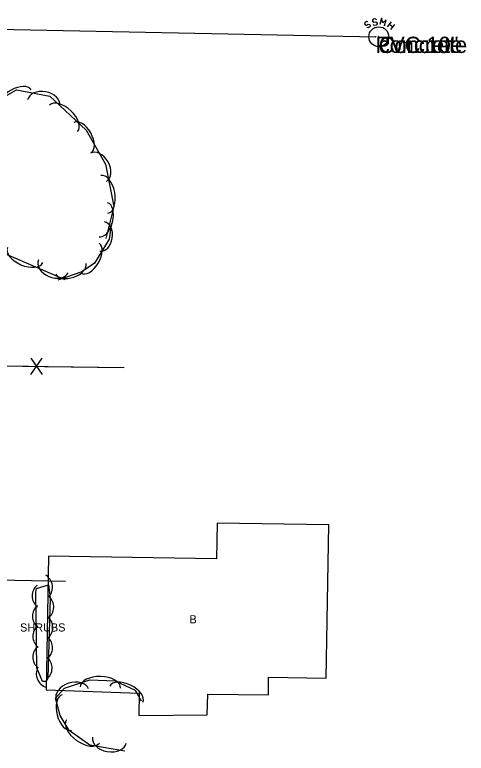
# Model space of a CAD drawing. Extents: x 1802180 to 1804859, y 572524 to 575172.
# Drawn here: x 1803803.6 to 1803942.1, y 574509.5 to 574736.5 of the extents above; entities that cross this region are included whole.
import ezdxf

# ---------------------------------------------------------------- set-up
doc = ezdxf.new("R2010")
doc.units = 0
for name, color, linetype in [('S_BUILDING', 7, 'Continuous'), ('S_BUILDING_ANNOT', 7, 'Continuous'), ('S_FENCE', 7, 'Continuous'), ('S_MANHOLE_ANNOT', 7, 'Continuous'), ('S_SANITARY_SEWER', 7, 'Continuous'), ('S_SANITARY_SEWER_ANNOT', 7, 'Continuous'), ('S_TREE', 7, 'Continuous'), ('S_TREE_ANNOT', 7, 'Continuous'), ('S_UTL_PT_SYM', 7, 'Continuous')]:
    doc.layers.add(name, color=color, linetype=linetype)

msp = doc.modelspace()

# ---------------------------------------------------------------- linework, layer by layer
at = {"layer": 'S_BUILDING'}
msp.add_lwpolyline([(1803865.43, 574569.24), (1803813.87, 574570.12), (1803813.18, 574528.96), (1803841.72, 574527.97), (1803841.59, 574521.14), (1803862.6, 574521.27), (1803862.86, 574527.68), (1803881.46, 574527.45), (1803881.47, 574532.86), (1803899.18, 574532.58), (1803899.92, 574579.72), (1803865.67, 574580.24), (1803865.43, 574569.24)], dxfattribs=at)
at = {"layer": 'S_FENCE'}
for p, q in [((1803808.43, 574625.93), (1803812, 574630.9)), ((1803808.49, 574630.94), (1803811.94, 574625.89)), ((1803783.29, 574628.75), (1803837.14, 574628.08)), ((1803785.29, 574563.13), (1803819.14, 574562.38))]:
    msp.add_line(p, q, dxfattribs=at)
for points in [[(1803783.29, 574628.75), (1803807.77, 574628.45)], [(1803812.67, 574628.39), (1803837.14, 574628.08)], [(1803803.75, 574562.72), (1803819.14, 574562.38)]]:
    msp.add_lwpolyline(points, dxfattribs=at)
at = {"layer": 'S_SANITARY_SEWER'}
for p, q in [((1803582.81, 574736.49), (1803914.33, 574729.75)), ((1803910.96, 574734.05), (1803910.88, 574733.66)), ((1803910.88, 574733.66), (1803911.08, 574733.39)), ((1803911.5, 574734.44), (1803910.96, 574734.05)), ((1803911.08, 574733.39), (1803911.5, 574733.27)), ((1803911.93, 574734.36), (1803911.5, 574734.44)), ((1803911.5, 574733.27), (1803912.04, 574733.62)), ((1803912.04, 574733.62), (1803912.51, 574733.54)), ((1803912.51, 574733.54), (1803912.66, 574733.27)), ((1803912.66, 574733.27), (1803912.59, 574732.85)), ((1803917.93, 574732.81), (1803919.17, 574734.28)), ((1803918.59, 574733.58), (1803919.56, 574732.77)), ((1803920.14, 574733.47), (1803918.9, 574731.99)), ((1803912.04, 574732.46), (1803911.66, 574732.54)), ((1803912.59, 574732.85), (1803912.04, 574732.46))]:
    msp.add_line(p, q, dxfattribs=at)
for points in [[(1803914.6, 574734.98), (1803914.25, 574735.25), (1803913.59, 574735.17), (1803913.36, 574734.82), (1803913.4, 574734.51), (1803913.75, 574734.2), (1803914.37, 574734.32), (1803914.76, 574734.01), (1803914.8, 574733.7), (1803914.52, 574733.31), (1803913.9, 574733.23), (1803913.56, 574733.51)], [(1803917.04, 574733.12), (1803917.59, 574734.98), (1803916.54, 574733.97), (1803916.15, 574735.4), (1803915.61, 574733.54)]]:
    msp.add_lwpolyline(points, dxfattribs=at)
msp.add_circle((1803915.29, 574729.74), 3.05, dxfattribs=at)
at = {"layer": 'S_TREE'}
for points in [[(1803818.99, 574655.01), (1803800.11, 574663.18), (1803781.57, 574668.1), (1803768.2, 574667.69), (1803754.34, 574668.35), (1803744.94, 574675.2), (1803742.42, 574684.43), (1803746.58, 574693.82), (1803753.83, 574697.99), (1803766.17, 574692.77), (1803777.95, 574690.27), (1803788.97, 574699.97), (1803794.69, 574708.13), (1803804.07, 574713.38), (1803814.36, 574711.52), (1803825.49, 574701), (1803831.44, 574690.55), (1803833.93, 574677.51), (1803831.48, 574667.76)], [(1803833.27, 574672.48), (1803832.49, 574667.56), (1803827.99, 574660.15), (1803824.16, 574657.5), (1803816.79, 574654.94)], [(1803810.27, 574535.77), (1803810.06, 574558.92), (1803810.19, 574560.13), (1803813.88, 574561.23), (1803814.44, 574557.33), (1803813.72, 574532.56), (1803813.05, 574531.61), (1803812.04, 574531.61), (1803810.27, 574535.77)], [(1803837.3, 574510.17), (1803826.54, 574512.04), (1803820.22, 574516.52), (1803817.45, 574521.12), (1803816.07, 574526.44), (1803818.85, 574529.47), (1803826.58, 574532.04), (1803834.37, 574531.82), (1803840.52, 574528.85), (1803842.37, 574525.63)]]:
    msp.add_lwpolyline(points, dxfattribs=at)
for centre, start, end in [((1803810.85, 574560.52), 317.4101, 59.007), ((1803813.16, 574557.88), 129.7234, 231.3203), ((1803811.22, 574554.44), 307.5336, 49.1305), ((1803813.26, 574551.63), 129.7234, 231.3203), ((1803810.95, 574548.16), 307.5336, 49.1305), ((1803813.4, 574545.41), 129.7234, 231.3203), ((1803810.86, 574541.94), 307.5336, 49.1305), ((1803813.37, 574539.12), 129.7234, 231.3203), ((1803810.72, 574535.69), 307.5336, 49.1305), ((1803814.42, 574533.93), 152.3074, 253.9043)]:
    msp.add_arc(centre, 4.29, start, end, dxfattribs=at)
for centre, major_axis, ratio in [((1803803.84, 574710.81), (-4.69, -2.63), 0.540699), ((1803812.41, 574709.44), (-4.91, 0.89), 0.685311), ((1803818.54, 574704.63), (-4.29, 4.05), 0.55008), ((1803824.32, 574698.75), (-2.66, 4.67), 0.540699), ((1803829.22, 574689.61), (-2.47, 4.33), 0.685311), ((1803831.04, 574681.28), (-1.11, 5.8), 0.55008), ((1803830.72, 574673.5), (1.31, 5.22), 0.540699), ((1803830.4, 574668.32), (0.7, 4.5), 0.685311), ((1803826.64, 574661.67), (2.8, 4.61), 0.55008), ((1803806.71, 574662.65), (5.42, -2.35), 0.55008), ((1803815.36, 574659.19), (4.57, -1.98), 0.685311), ((1803820.79, 574658.39), (4.64, 1.61), 0.540699), ((1803821.22, 574527.6), (-4.97, -1.66), 0.68531), ((1803829.82, 574529.71), (-6.2, 0.18), 0.550078), ((1803837.79, 574527.68), (-5.09, 2.46), 0.540697), ((1803819.53, 574522.04), (1.42, -5.47), 0.540698), ((1803824.49, 574516.24), (5.06, -3.59), 0.550077), ((1803832.57, 574513.55), (5.16, -0.9), 0.685309)]:
    msp.add_ellipse(centre, major_axis=major_axis, ratio=ratio, start_param=3.141593, end_param=6.283185, dxfattribs=at)
at = {"layer": 'S_UTL_PT_SYM'}
for points in [[(1803914.33, 574729.75), (1803914.33, 574729.8), (1803914.33, 574729.75), (1803914.28, 574729.75), (1803914.33, 574729.75), (1803914.33, 574729.7), (1803914.33, 574729.75), (1803914.38, 574729.75)], [(1803915.28, 574729.78), (1803915.28, 574729.83), (1803915.28, 574729.78), (1803915.23, 574729.78), (1803915.28, 574729.78), (1803915.28, 574729.73), (1803915.28, 574729.78), (1803915.33, 574729.78)]]:
    msp.add_lwpolyline(points, dxfattribs=at)

# ---------------------------------------------------------------- texts
at = {"layer": 'S_BUILDING_ANNOT'}
msp.add_text('B', height=2.5, dxfattribs=at).set_placement((1803857.18, 574549.43))
at = {"layer": 'S_MANHOLE_ANNOT'}
msp.add_text('concrete   ', height=5, dxfattribs=at).set_placement((1803915.28, 574724.78))
at = {"layer": 'S_SANITARY_SEWER_ANNOT'}
for s, p in [('PVC 10" ', (1803914.33, 574724.75)), ('Concrete ', (1803915.29, 574724.74))]:
    msp.add_text(s, height=5, dxfattribs=at).set_placement(p)
at = {"layer": 'S_TREE_ANNOT'}
msp.add_text('SHRUBS', height=2.5, dxfattribs=at).set_placement((1803805.16, 574546.92))

doc.saveas('drawing.dxf')
